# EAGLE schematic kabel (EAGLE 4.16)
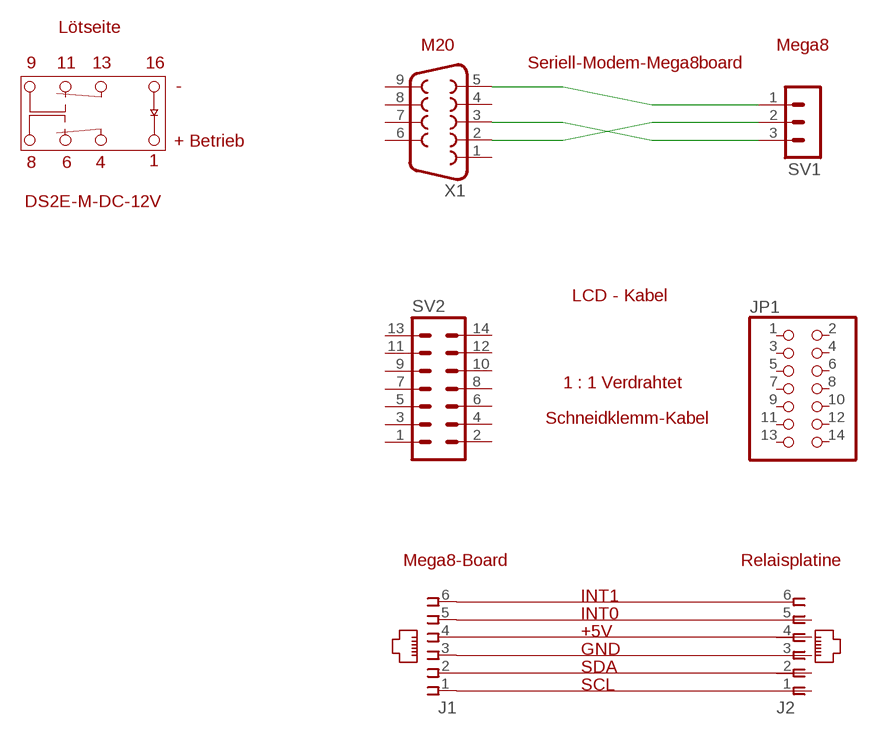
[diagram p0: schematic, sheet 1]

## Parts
J1  520250-3  [520250-3]
J2  520250-3  [520250-3]
JP1  PINHD-2X7  [2X07]
SV1  MA03-1  [MA03-1]
SV2  14P  [14P]
X1  F09D  [F09D]

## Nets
N$1: SV1.1 X1.5
N$2: SV1.2 X1.2
N$3: SV1.3 X1.3
Unconnected: J1.1 J1.2 J1.3 J1.4 J1.5 J1.6 J2.1 J2.2 J2.3 J2.4 J2.5 J2.6 JP1.1 JP1.2 JP1.3 JP1.4 JP1.5 JP1.6 JP1.7 JP1.8 JP1.9 JP1.10 JP1.11 JP1.12 JP1.13 JP1.14 SV2.1 SV2.2 SV2.3 SV2.4 SV2.5 SV2.6 SV2.7 SV2.8 SV2.9 SV2.10 SV2.11 SV2.12 SV2.13 SV2.14 X1.1 X1.4 X1.6 X1.7 X1.8 X1.9

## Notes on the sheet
- Lötseite
- M20 | Mega8
- 9 | 11 | 13 | 16 | Seriell-Modem-Mega8board
- -
- + Betrieb
- 8 | 6 | 4 | 1
- DS2E-M-DC-12V
- LCD - Kabel
- 1 : 1 Verdrahtet
- Schneidklemm-Kabel
- Mega8-Board | Relaisplatine
- INT1
- INT0
- +5V
- GND
- SDA
- SCL

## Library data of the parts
J1 J2 = con-amp:520250-3: AMP connector
JP1 = pinhead:PINHD-2X7: PIN HEADER
SV1 = con-lstb:MA03-1: PIN HEADER
SV2 = con-dil:14P: DIL CABLE CONNECTOR
X1 = con-subd:F09: SUB-D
